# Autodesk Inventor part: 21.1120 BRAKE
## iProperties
Created: 2007-03
Part Number: 21.1120 BRAKE
Material: Phenolic
Document SubType Name: Modeling
Designer: Andy Moles
Density: 1.38 g/cm^3
Author: Andy Moles
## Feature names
1. Base1
